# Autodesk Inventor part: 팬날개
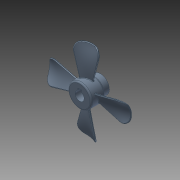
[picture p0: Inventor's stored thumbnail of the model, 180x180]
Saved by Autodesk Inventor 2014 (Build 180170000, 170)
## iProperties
Company: 한국ATC센터
Created: 2016-06
Part Number: 팬날개
Document SubType Name: Modeling
Designer: mdu
Density: 1.06 g/cm^3
Material: ABS 플라스틱
Mass: 29.2288 g
Surface Area: 148.227 cm^2
Volume: 27.5744 cm^3
Appearance: 강청색
Author: mdu
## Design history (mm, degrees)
sketch "스케치1"
  geometry: L1 (-15, 0)-(15, 0); L2 (-15, 0)-(-15, 17); L3 (-15, 17)-(5, 17); L4 (5, 17)-(5, 13); L5 (5, 13)-(15, 13); L6 (15, 13)-(15, 0); 2 further points
  constraints: 12 end point, 3 parallel, 2 perpendicular, 1 coincident, 1 horizontal, 1 midpoint
  dimensions: "d0" = 30 distance of L1.start L1.end; "d8" = 34 diameter of L3 L1; "d10" = 26 diameter of L5 L1; "d32" = 20 distance of L2.end L3.end
revolve "회전1" sketch "스케치1" stored, may be unused: angle "d11" = 90 deg
node "작업 평면2"
sketch "스케치7"
  geometry: L1 (-15, 17)-(5, 17) reference; L2 (-15, -17)-(5, -17) reference; L3 (-5, 17)-(-5, -17); A1 r 35 centre (-36.399, -13.457) between (-2, -7) and (-8, 7); 1 further point
  constraints: 2 end point, 2 midpoint, 2 point on circle, 1 centre point
  dimensions: "d36" = 35 radius of A1; "d37" = 10 distance from line of A1.start L2; "d38" = 10 distance from line of A1.end L1; "d45" = 3 distance from line of A1.end L3; "d46" = 3 distance from line of A1.start L3
sketch "3D 스케치1"
  geometry: L1 through (0, 0) direction (1, 0) reference; L2 through (0, 0) direction (1, 0) reference; 13 other entities
  constraints: 2 collinear
  node "투영 원본 위치 스케치7"
sketch "스케치8"
  geometry: L1 (-15, 17)-(5, 17) reference; L2 (-15, -17)-(5, -17) reference; L3 (-5, 17)-(-5, -17); A1 r 30 centre (-28.74, -3.591) between (-3, -19) and (-9, 19); 1 further point
  constraints: 2 end point, 2 midpoint, 2 point on circle, 1 centre point
  dimensions: "d43" = 30 radius of A1; "d47" = 4 distance from line of A1.end L3; "d48" = 2 distance from line of A1.start L3; "d58" = 2 distance from line of A1.end L1; "d59" = 2 distance from line of A1.start L2
sketch "3D 스케치2"
sketch "3D 스케치3"
feature "경계 패치1" sketch "3D 스케치2", "3D 스케치3" dims "d50" = 0
feature "연장1" dims "d55" = 2
feature "두껍게 하기1" dims "d51" = 2, "d52" = 2
sketch "스케치9"
  geometry: C1 r 59 at (0, 0); 1 further point
  constraints: 1 centre point, 1 coincident
  dimensions: "d60" = 118 diameter of C1
extrude "돌출2" sketch "스케치9" distance "d62" = 200; taper "d63" = 0 deg
fillet "모깎기6" dims "d64" = 10
fillet "모깎기7" dims "d66" = 0.8
fillet "모깎기8" dims "d67" = 0.8
sketch "스케치2"
  geometry: L1 (-2.5, 6)-(-2.5, 8.8); L2 (-2.5, 8.8)-(2.5, 8.8); L3 (2.5, 8.8)-(2.5, 6); A1 r 6.5 centre (0, 0) between (-2.5, 6) and (2.5, 6); 1 further point
  constraints: 6 end point, 2 parallel, 2 point on circle, 1 centre point, 1 coincident, 1 horizontal, 1 vertical
  dimensions: "d12" = 13 diameter of A1; "d13" = 5 distance of L1.end L2.end; "d14" = 15.3 dimension on A1 L2 (computed from d12)
extrude "돌출1" cut sketch "스케치2" stored distance "d15" = 10; taper "d16" = 0 deg
chamfer "모따기1" distance "d17" = 1; stored, may be unused: second distance "d18" = 2, angle "d19" = 45 deg
node "작업 평면1"
sketch "스케치3"
  geometry: L1 (5, -13)-(5, 13) reference; 3 further points
  constraints: 1 horizontal alignment, 1 midpoint
  dimensions: "d20" = 5 distance from line of L1 point (0, 0)
hole "구멍1" sketch "스케치3" at (0, 0) diameter "d21" = 3.242; stored, may be unused: countersink angle "d25" = 90 deg, drill point angle "d27" = 118 deg; dims "d22" = 6, "d23" = 4, "d24" = 2, "d26" = 8
fillet "모깎기9" dims "d77" = 2
fillet "모깎기10" dims "d78" = 2
fillet "모깎기11" dims "d79" = 2
node "솔리드1"
pattern_circular "원형 패턴1" dims "d69" = 360 deg
pattern_circular "원형 패턴2" dims angle "d72" = 360 deg
pattern_circular "원형 패턴3" dims angle "d75" = 360 deg
node "투영 원본 위치 스케치8"
node "곡면1"
node "곡면2"
node "곡면3"
node "곡면4"
feature "경계 패치2"
feature "경계 패치3"
feature "경계 패치4"
